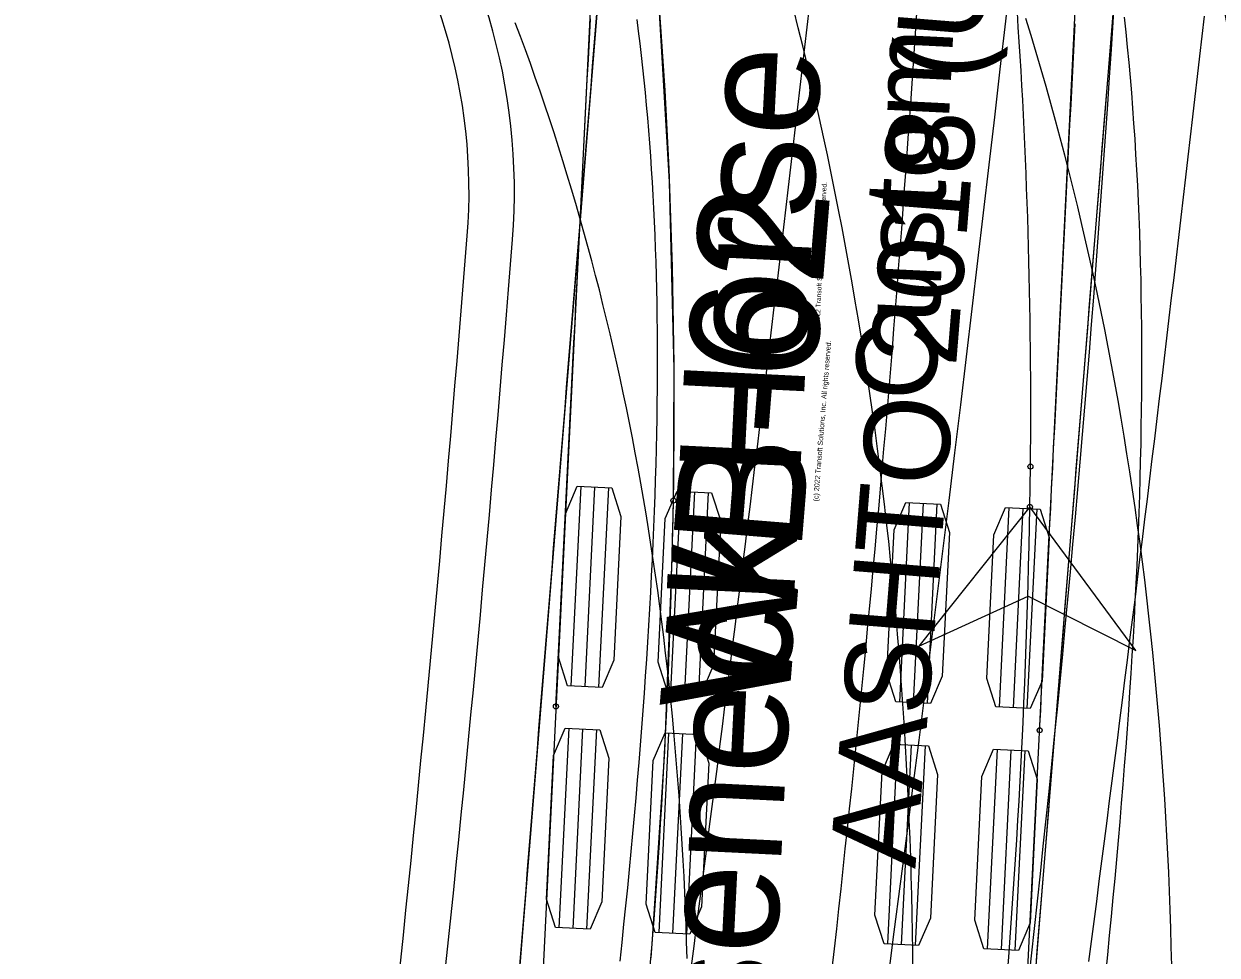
# Model space of a CAD drawing. Extents: x -14 to 1565148, y -25 to 642856.
# Drawn here: x 1564799.31 to 1564819.02, y 636248.55 to 636263.93 of the extents above; entities that cross this region are included whole.
import ezdxf

# ---------------------------------------------------------------- set-up
doc = ezdxf.new("R2010")
doc.units = 0
for name, color, linetype in [('GE_X_Alignment', 7, 'Continuous'), ('MT_P_Cells', 7, 'Continuous'), ('PF_P_Grade_Line', 7, 'Continuous'), ('PV_P_Curb', 7, 'Continuous'), ('PV_P_EOP', 7, 'Continuous'), ('TR_Turning_Path25', 7, 'Continuous'), ('TR_Turning_Path27', 7, 'Continuous')]:
    doc.layers.add(name, color=color, linetype=linetype)

msp = doc.modelspace()

# ---------------------------------------------------------------- linework, layer by layer
at = {"layer": 'GE_X_Alignment'}
for centre, radius, start, end in [((1564797.408, 636261.157), 9.25, 355.4736, 79.0428), ((1564323.889, 636298.643), 484.25, 352.33607, 355.47361)]:
    msp.add_arc(centre, radius, start, end, dxfattribs=at)
at = {"layer": 'MT_P_Cells'}
for points in [[(1564810.331, 636248.364), (1564810.375, 636248.694), (1564810.418, 636249.024), (1564810.461, 636249.353), (1564810.504, 636249.683), (1564810.547, 636250.013), (1564810.59, 636250.343), (1564810.633, 636250.673), (1564810.675, 636251.002), (1564810.718, 636251.332), (1564810.76, 636251.662), (1564810.802, 636251.992), (1564810.844, 636252.322), (1564810.886, 636252.652), (1564810.928, 636252.982), (1564810.97, 636253.311), (1564811.012, 636253.641), (1564811.053, 636253.971), (1564811.094, 636254.301), (1564811.136, 636254.631), (1564811.177, 636254.961), (1564811.218, 636255.291), (1564811.259, 636255.621), (1564811.3, 636255.951), (1564811.34, 636256.281), (1564811.381, 636256.611), (1564811.421, 636256.942), (1564811.462, 636257.272), (1564811.502, 636257.602), (1564811.542, 636257.932), (1564811.582, 636258.262), (1564811.622, 636258.592), (1564811.661, 636258.922), (1564811.701, 636259.253), (1564811.74, 636259.583), (1564811.78, 636259.913), (1564811.819, 636260.243), (1564811.858, 636260.573), (1564811.897, 636260.904), (1564811.936, 636261.234), (1564811.975, 636261.564), (1564812.013, 636261.894), (1564812.052, 636262.225), (1564812.09, 636262.555), (1564812.129, 636262.885), (1564812.167, 636263.216), (1564812.205, 636263.546), (1564812.243, 636263.877), (1564812.28, 636264.207)], [(1564809.155, 636248.448), (1564809.187, 636248.752), (1564809.218, 636249.056), (1564809.249, 636249.358), (1564809.279, 636249.659), (1564809.308, 636249.959), (1564809.336, 636250.257), (1564809.364, 636250.554), (1564809.391, 636250.849), (1564809.417, 636251.143), (1564809.442, 636251.435), (1564809.466, 636251.726), (1564809.49, 636252.015), (1564809.512, 636252.303), (1564809.534, 636252.589), (1564809.555, 636252.873), (1564809.575, 636253.156), (1564809.594, 636253.437), (1564809.612, 636253.716), (1564809.63, 636253.993), (1564809.646, 636254.268), (1564809.661, 636254.542), (1564809.675, 636254.813), (1564809.689, 636255.083), (1564809.701, 636255.35), (1564809.713, 636255.615), (1564809.723, 636255.879), (1564809.733, 636256.14), (1564809.741, 636256.399), (1564809.748, 636256.656), (1564809.755, 636256.91), (1564809.76, 636257.163), (1564809.765, 636257.413), (1564809.768, 636257.66), (1564809.77, 636257.906), (1564809.772, 636258.148), (1564809.772, 636258.389), (1564809.772, 636258.627), (1564809.77, 636258.862), (1564809.767, 636259.092), (1564809.764, 636259.32), (1564809.759, 636259.548), (1564809.754, 636259.774), (1564809.748, 636259.998), (1564809.74, 636260.221), (1564809.732, 636260.443), (1564809.722, 636260.664), (1564809.712, 636260.883), (1564809.7, 636261.101), (1564809.688, 636261.318), (1564809.674, 636261.533), (1564809.66, 636261.747), (1564809.644, 636261.959), (1564809.628, 636262.17), (1564809.61, 636262.38), (1564809.592, 636262.588), (1564809.572, 636262.795), (1564809.552, 636263), (1564809.53, 636263.204), (1564809.508, 636263.407), (1564809.484, 636263.608), (1564809.459, 636263.808), (1564809.434, 636264.006)], [(1564816.896, 636248.438), (1564816.939, 636248.77), (1564816.983, 636249.102), (1564817.026, 636249.434), (1564817.069, 636249.766), (1564817.112, 636250.098), (1564817.155, 636250.43), (1564817.197, 636250.763), (1564817.24, 636251.095), (1564817.282, 636251.427), (1564817.325, 636251.759), (1564817.367, 636252.091), (1564817.409, 636252.424), (1564817.451, 636252.756), (1564817.493, 636253.088), (1564817.534, 636253.42), (1564817.576, 636253.753), (1564817.617, 636254.085), (1564817.659, 636254.417), (1564817.7, 636254.75), (1564817.741, 636255.082), (1564817.782, 636255.414), (1564817.823, 636255.747), (1564817.864, 636256.079), (1564817.904, 636256.412), (1564817.945, 636256.744), (1564817.985, 636257.077), (1564818.025, 636257.409), (1564818.066, 636257.742), (1564818.106, 636258.074), (1564818.145, 636258.407), (1564818.185, 636258.739), (1564818.225, 636259.072), (1564818.264, 636259.404), (1564818.304, 636259.737), (1564818.343, 636260.069), (1564818.382, 636260.402), (1564818.421, 636260.735), (1564818.46, 636261.067), (1564818.499, 636261.4), (1564818.538, 636261.732), (1564818.576, 636262.065), (1564818.615, 636262.398), (1564818.653, 636262.731), (1564818.691, 636263.063), (1564818.73, 636263.396), (1564818.768, 636263.729), (1564818.805, 636264.061)], [(1564817.176, 636248.236), (1564817.208, 636248.553), (1564817.24, 636248.869), (1564817.27, 636249.184), (1564817.3, 636249.499), (1564817.329, 636249.812), (1564817.358, 636250.125), (1564817.385, 636250.437), (1564817.412, 636250.748), (1564817.438, 636251.058), (1564817.463, 636251.367), (1564817.488, 636251.674), (1564817.511, 636251.981), (1564817.534, 636252.286), (1564817.555, 636252.591), (1564817.576, 636252.894), (1564817.595, 636253.196), (1564817.614, 636253.496), (1564817.632, 636253.796), (1564817.649, 636254.094), (1564817.664, 636254.39), (1564817.679, 636254.685), (1564817.693, 636254.979), (1564817.705, 636255.271), (1564817.717, 636255.562), (1564817.727, 636255.851), (1564817.737, 636256.138), (1564817.745, 636256.424), (1564817.752, 636256.708), (1564817.758, 636256.99), (1564817.763, 636257.271), (1564817.767, 636257.55), (1564817.77, 636257.827), (1564817.772, 636258.102), (1564817.772, 636258.375), (1564817.772, 636258.646), (1564817.77, 636258.915), (1564817.767, 636259.179), (1564817.763, 636259.441), (1564817.758, 636259.704), (1564817.752, 636259.965), (1564817.744, 636260.226), (1564817.736, 636260.486), (1564817.726, 636260.746), (1564817.715, 636261.004), (1564817.703, 636261.262), (1564817.689, 636261.519), (1564817.675, 636261.775), (1564817.659, 636262.031), (1564817.642, 636262.285), (1564817.623, 636262.539), (1564817.604, 636262.792), (1564817.583, 636263.044), (1564817.561, 636263.295), (1564817.537, 636263.545), (1564817.512, 636263.795), (1564817.486, 636264.043)]]:
    msp.add_lwpolyline(points, dxfattribs=at)
msp.add_arc((1563898.73, 636368.57), 922.742, 351.014658, 354.185106, dxfattribs=at)
at = {"layer": 'PF_P_Grade_Line'}
for points in [[(1564812.657, 636248.323), (1564812.694, 636248.652), (1564812.731, 636248.982), (1564812.767, 636249.312), (1564812.803, 636249.642), (1564812.839, 636249.972), (1564812.874, 636250.302), (1564812.909, 636250.632), (1564812.944, 636250.962), (1564812.979, 636251.292), (1564813.013, 636251.622), (1564813.047, 636251.952), (1564813.08, 636252.282), (1564813.113, 636252.613), (1564813.146, 636252.943), (1564813.178, 636253.273), (1564813.21, 636253.603), (1564813.242, 636253.934), (1564813.273, 636254.264), (1564813.304, 636254.594), (1564813.335, 636254.925), (1564813.365, 636255.255), (1564813.396, 636255.586), (1564813.425, 636255.916), (1564813.455, 636256.247), (1564813.484, 636256.577), (1564813.512, 636256.908), (1564813.541, 636257.239), (1564813.569, 636257.569), (1564813.596, 636257.9), (1564813.624, 636258.231), (1564813.651, 636258.562), (1564813.677, 636258.892), (1564813.704, 636259.223), (1564813.73, 636259.554), (1564813.755, 636259.885), (1564813.781, 636260.216), (1564813.806, 636260.547), (1564813.83, 636260.878), (1564813.854, 636261.208), (1564813.878, 636261.539), (1564813.902, 636261.87), (1564813.925, 636262.202), (1564813.948, 636262.533), (1564813.971, 636262.864), (1564813.993, 636263.195), (1564814.015, 636263.526), (1564814.037, 636263.857), (1564814.058, 636264.188)], [(1564810.26, 636248.491), (1564810.253, 636248.763), (1564810.244, 636249.034), (1564810.234, 636249.304), (1564810.222, 636249.574), (1564810.21, 636249.843), (1564810.196, 636250.111), (1564810.181, 636250.379), (1564810.165, 636250.646), (1564810.148, 636250.912), (1564810.129, 636251.178), (1564810.109, 636251.443), (1564810.088, 636251.707), (1564810.066, 636251.971), (1564810.042, 636252.234), (1564810.018, 636252.496), (1564809.992, 636252.757), (1564809.965, 636253.018), (1564809.936, 636253.278), (1564809.906, 636253.537), (1564809.875, 636253.796), (1564809.843, 636254.054), (1564809.81, 636254.311), (1564809.775, 636254.568), (1564809.739, 636254.823), (1564809.701, 636255.078), (1564809.663, 636255.332), (1564809.623, 636255.586), (1564809.582, 636255.839), (1564809.539, 636256.09), (1564809.496, 636256.342), (1564809.451, 636256.592), (1564809.404, 636256.842), (1564809.357, 636257.091), (1564809.308, 636257.339), (1564809.258, 636257.586), (1564809.206, 636257.833), (1564809.154, 636258.078), (1564809.1, 636258.323), (1564809.045, 636258.567), (1564808.988, 636258.811), (1564808.93, 636259.053), (1564808.871, 636259.295), (1564808.811, 636259.536), (1564808.749, 636259.776), (1564808.686, 636260.015), (1564808.622, 636260.253), (1564808.557, 636260.491), (1564808.49, 636260.728), (1564808.422, 636260.964), (1564808.352, 636261.199), (1564808.282, 636261.433), (1564808.21, 636261.666), (1564808.137, 636261.898), (1564808.062, 636262.13), (1564807.987, 636262.361), (1564807.91, 636262.59), (1564807.831, 636262.819), (1564807.752, 636263.047), (1564807.671, 636263.274), (1564807.589, 636263.5), (1564807.506, 636263.725), (1564807.421, 636263.95)], [(1564818.265, 636248.376), (1564818.258, 636248.683), (1564818.249, 636248.99), (1564818.239, 636249.296), (1564818.228, 636249.602), (1564818.215, 636249.908), (1564818.201, 636250.213), (1564818.186, 636250.518), (1564818.169, 636250.823), (1564818.151, 636251.127), (1564818.131, 636251.431), (1564818.11, 636251.735), (1564818.087, 636252.038), (1564818.063, 636252.34), (1564818.038, 636252.643), (1564818.011, 636252.945), (1564817.982, 636253.246), (1564817.953, 636253.547), (1564817.921, 636253.848), (1564817.889, 636254.148), (1564817.854, 636254.447), (1564817.819, 636254.747), (1564817.781, 636255.045), (1564817.743, 636255.344), (1564817.702, 636255.641), (1564817.661, 636255.939), (1564817.617, 636256.235), (1564817.572, 636256.532), (1564817.526, 636256.827), (1564817.478, 636257.122), (1564817.429, 636257.417), (1564817.378, 636257.711), (1564817.325, 636258.005), (1564817.271, 636258.297), (1564817.215, 636258.59), (1564817.158, 636258.881), (1564817.099, 636259.173), (1564817.039, 636259.463), (1564816.977, 636259.753), (1564816.913, 636260.042), (1564816.848, 636260.331), (1564816.781, 636260.619), (1564816.713, 636260.906), (1564816.643, 636261.193), (1564816.571, 636261.479), (1564816.498, 636261.764), (1564816.424, 636262.048), (1564816.347, 636262.332), (1564816.269, 636262.615), (1564816.19, 636262.898), (1564816.109, 636263.179), (1564816.026, 636263.46), (1564815.942, 636263.74), (1564815.856, 636264.02)]]:
    msp.add_lwpolyline(points, dxfattribs=at)
msp.add_arc((1564490.246, 636284.79), 327.714, 352.53249, 357.63053, dxfattribs=at)
at = {"layer": 'PV_P_Curb'}
for points in [[(1564810.034, 636256.055), (1564810.046, 636258.226), (1564809.971, 636261.319), (1564809.79, 636264.407), (1564809.501, 636267.487), (1564809.106, 636270.555), (1564809.014, 636271.167)], [(1564809.665, 636248.499), (1564809.69, 636248.816), (1564809.714, 636249.133), (1564809.737, 636249.449), (1564809.759, 636249.766), (1564809.781, 636250.082), (1564809.802, 636250.398), (1564809.822, 636250.714), (1564809.841, 636251.03), (1564809.859, 636251.346), (1564809.876, 636251.662), (1564809.893, 636251.977), (1564809.909, 636252.293), (1564809.924, 636252.608), (1564809.938, 636252.923), (1564809.951, 636253.237), (1564809.964, 636253.552), (1564809.975, 636253.866), (1564809.986, 636254.182), (1564809.996, 636254.496), (1564810.005, 636254.811), (1564810.014, 636255.125), (1564810.021, 636255.441), (1564810.028, 636255.756), (1564810.034, 636256.073), (1564810.039, 636256.389), (1564810.043, 636256.708), (1564810.046, 636257.024), (1564810.047, 636257.344), (1564810.048, 636257.662), (1564810.047, 636257.984), (1564810.045, 636258.303), (1564810.042, 636258.626), (1564810.038, 636258.946), (1564810.033, 636259.27), (1564810.026, 636259.592), (1564810.018, 636259.917), (1564810.01, 636260.239), (1564809.999, 636260.565), (1564809.988, 636260.888), (1564809.976, 636261.214), (1564809.962, 636261.537), (1564809.947, 636261.862), (1564809.931, 636262.185), (1564809.914, 636262.51), (1564809.896, 636262.832), (1564809.876, 636263.155), (1564809.856, 636263.476), (1564809.834, 636263.797), (1564809.811, 636264.116)], [(1564812.986, 636259.651), (1564812.932, 636259.954), (1564812.877, 636260.256), (1564812.82, 636260.559), (1564812.761, 636260.861), (1564812.701, 636261.163), (1564812.64, 636261.464), (1564812.577, 636261.766), (1564812.513, 636262.066), (1564812.447, 636262.367), (1564812.38, 636262.667), (1564812.312, 636262.967), (1564812.242, 636263.267), (1564812.17, 636263.566), (1564812.097, 636263.865), (1564812.023, 636264.163)], [(1564813.991, 636248.304), (1564813.988, 636248.613), (1564813.984, 636248.922), (1564813.978, 636249.23), (1564813.971, 636249.539), (1564813.963, 636249.848), (1564813.954, 636250.156), (1564813.943, 636250.465), (1564813.931, 636250.773), (1564813.918, 636251.081), (1564813.903, 636251.389), (1564813.887, 636251.697), (1564813.87, 636252.005), (1564813.851, 636252.313), (1564813.831, 636252.621), (1564813.81, 636252.928), (1564813.787, 636253.236), (1564813.763, 636253.543), (1564813.738, 636253.85), (1564813.711, 636254.157), (1564813.683, 636254.464), (1564813.653, 636254.771), (1564813.622, 636255.077), (1564813.59, 636255.383), (1564813.556, 636255.69), (1564813.521, 636255.996), (1564813.484, 636256.301), (1564813.446, 636256.607), (1564813.407, 636256.912), (1564813.366, 636257.218), (1564813.323, 636257.523), (1564813.28, 636257.827), (1564813.234, 636258.132), (1564813.188, 636258.436), (1564813.14, 636258.74), (1564813.09, 636259.044), (1564813.039, 636259.348), (1564812.986, 636259.651)], [(1564815.923, 636255.95), (1564815.928, 636256.283), (1564815.932, 636256.617)], [(1564809.393, 636245.549), (1564809.683, 636248.729), (1564809.89, 636251.912), (1564810.013, 636255.099), (1564810.034, 636256.055)], [(1564815.923, 636255.95), (1564814.086, 636253.648), (1564815.895, 636254.478), (1564817.671, 636253.58), (1564815.923, 636255.95)]]:
    msp.add_lwpolyline(points, dxfattribs=at)
msp.add_lwpolyline([(1564815.923, 636255.95), (1564814.086, 636253.648), (1564815.895, 636254.478), (1564817.671, 636253.58)], close=True, dxfattribs=at)
for centre in [(1564815.932, 636256.617), (1564815.932, 636256.617), (1564810.034, 636256.055), (1564810.034, 636256.055), (1564815.923, 636255.95), (1564815.923, 636255.95)]:
    msp.add_circle(centre, 0.0417, dxfattribs=at)
for centre, radius, start, end in [((1564760.333, 636253.08), 59.839, 7.57218, 39.87786), ((1564720.886, 636257.63), 95.051, 359.38909, 8.73292), ((1564687.778, 636258.238), 128.165, 354.34466, 358.9773)]:
    msp.add_arc(centre, radius, start, end, dxfattribs=at)
at = {"layer": 'PV_P_EOP'}
for centre, radius, start, end in [((1564797.408, 636261.157), 10, 355.4736, 79.0428), ((1564797.408, 636261.157), 9.25, 355.4736, 79.0428), ((1564323.889, 636298.643), 484.25, 352.33607, 355.47361), ((1564323.889, 636298.643), 485, 352.33607, 355.47361)]:
    msp.add_arc(centre, radius, start, end, dxfattribs=at)
at = {"layer": 'TR_Turning_Path25'}
for p, q in [((1564809.376, 636278.624), (1564807.601, 636242.667)), ((1564815.591, 636242.273), (1564817.366, 636278.229)), ((1564808.503, 636256.289), (1564808.34, 636252.993)), ((1564808.732, 636256.278), (1564808.569, 636252.982)), ((1564808.96, 636256.267), (1564808.798, 636252.971)), ((1564810.151, 636256.208), (1564809.988, 636252.912)), ((1564810.38, 636256.197), (1564810.217, 636252.901)), ((1564810.608, 636256.186), (1564810.446, 636252.89)), ((1564813.929, 636256.022), (1564813.767, 636252.726)), ((1564814.158, 636256.01), (1564813.996, 636252.714)), ((1564814.387, 636255.999), (1564814.224, 636252.703)), ((1564815.577, 636255.94), (1564815.415, 636252.644)), ((1564815.806, 636255.929), (1564815.644, 636252.633)), ((1564816.035, 636255.918), (1564815.872, 636252.622)), ((1564808.305, 636252.294), (1564808.143, 636248.998)), ((1564808.534, 636252.283), (1564808.372, 636248.987)), ((1564808.763, 636252.272), (1564808.6, 636248.976)), ((1564809.953, 636252.213), (1564809.791, 636248.917)), ((1564810.182, 636252.202), (1564810.02, 636248.906)), ((1564810.411, 636252.19), (1564810.248, 636248.894)), ((1564813.732, 636252.026), (1564813.569, 636248.73)), ((1564813.961, 636252.015), (1564813.798, 636248.719)), ((1564814.19, 636252.004), (1564814.027, 636248.708)), ((1564815.38, 636251.945), (1564815.217, 636248.649)), ((1564815.609, 636251.934), (1564815.446, 636248.638)), ((1564815.838, 636251.922), (1564815.675, 636248.626))]:
    msp.add_line(p, q, dxfattribs=at)
for points in [[(1564808.094, 636252.655), (1564808.11, 636252.988), (1564808.127, 636253.321), (1564808.143, 636253.654), (1564808.16, 636253.988), (1564808.176, 636254.322), (1564808.193, 636254.656), (1564808.209, 636254.99), (1564808.226, 636255.324), (1564808.242, 636255.658), (1564808.259, 636255.992), (1564808.275, 636256.326), (1564808.292, 636256.66), (1564808.309, 636256.994), (1564808.325, 636257.328), (1564808.342, 636257.662), (1564808.359, 636257.996), (1564808.375, 636258.33), (1564808.392, 636258.665), (1564808.409, 636258.999), (1564808.425, 636259.333), (1564808.442, 636259.667), (1564808.459, 636260.001), (1564808.476, 636260.335), (1564808.493, 636260.67), (1564808.51, 636261.004), (1564808.527, 636261.338), (1564808.544, 636261.672), (1564808.561, 636262.007), (1564808.578, 636262.341), (1564808.595, 636262.675), (1564808.612, 636263.01), (1564808.63, 636263.344), (1564808.647, 636263.678), (1564808.664, 636264.013)], [(1564816.084, 636252.261), (1564816.101, 636252.594), (1564816.117, 636252.927), (1564816.133, 636253.259), (1564816.15, 636253.593), (1564816.166, 636253.927), (1564816.183, 636254.261), (1564816.199, 636254.595), (1564816.216, 636254.928), (1564816.232, 636255.262), (1564816.249, 636255.596), (1564816.266, 636255.929), (1564816.282, 636256.263), (1564816.299, 636256.597), (1564816.315, 636256.93), (1564816.332, 636257.264), (1564816.349, 636257.597), (1564816.365, 636257.931), (1564816.382, 636258.265), (1564816.399, 636258.598), (1564816.415, 636258.932), (1564816.432, 636259.265), (1564816.449, 636259.599), (1564816.466, 636259.932), (1564816.483, 636260.266), (1564816.5, 636260.599), (1564816.517, 636260.932), (1564816.534, 636261.266), (1564816.551, 636261.599), (1564816.568, 636261.932), (1564816.585, 636262.266), (1564816.602, 636262.599), (1564816.619, 636262.932), (1564816.636, 636263.266), (1564816.653, 636263.599), (1564816.671, 636263.932)]]:
    msp.add_lwpolyline(points, dxfattribs=at)
for points in [[(1564808.446, 636256.292), (1564809.017, 636256.264), (1564809.167, 636255.794), (1564809.049, 636253.421), (1564808.855, 636252.968), (1564808.283, 636252.996), (1564808.134, 636253.466), (1564808.251, 636255.839)], [(1564810.094, 636256.211), (1564810.665, 636256.183), (1564810.815, 636255.713), (1564810.697, 636253.34), (1564810.503, 636252.887), (1564809.931, 636252.915), (1564809.782, 636253.385), (1564809.899, 636255.758)], [(1564813.873, 636256.024), (1564814.444, 636255.996), (1564814.593, 636255.526), (1564814.476, 636253.153), (1564814.281, 636252.7), (1564813.71, 636252.728), (1564813.561, 636253.198), (1564813.678, 636255.571)], [(1564815.521, 636255.943), (1564816.092, 636255.915), (1564816.241, 636255.445), (1564816.124, 636253.072), (1564815.929, 636252.619), (1564815.358, 636252.647), (1564815.209, 636253.117), (1564815.326, 636255.49)], [(1564808.249, 636252.297), (1564808.82, 636252.269), (1564808.969, 636251.799), (1564808.852, 636249.426), (1564808.657, 636248.973), (1564808.086, 636249.001), (1564807.937, 636249.471), (1564808.054, 636251.844)], [(1564809.897, 636252.216), (1564810.468, 636252.188), (1564810.617, 636251.718), (1564810.5, 636249.345), (1564810.305, 636248.892), (1564809.734, 636248.92), (1564809.585, 636249.39), (1564809.702, 636251.763)], [(1564813.675, 636252.029), (1564814.247, 636252.001), (1564814.396, 636251.531), (1564814.279, 636249.158), (1564814.084, 636248.705), (1564813.513, 636248.733), (1564813.363, 636249.203), (1564813.481, 636251.576)], [(1564815.323, 636251.948), (1564815.895, 636251.92), (1564816.044, 636251.45), (1564815.927, 636249.077), (1564815.732, 636248.624), (1564815.161, 636248.652), (1564815.011, 636249.122), (1564815.129, 636251.495)]]:
    msp.add_lwpolyline(points, close=True, dxfattribs=at)
for centre in [(1564808.094, 636252.655), (1564816.084, 636252.261)]:
    msp.add_circle(centre, 0.0417, dxfattribs=at)
at = {"layer": 'TR_Turning_Path27'}
for p, q in [((1564810.223, 636282.042), (1564806.356, 636234.269)), ((1564814.828, 636233.583), (1564818.695, 636281.357))]:
    msp.add_line(p, q, dxfattribs=at)
for points in [[(1564807.492, 636248.305), (1564807.519, 636248.637), (1564807.546, 636248.968), (1564807.573, 636249.3), (1564807.6, 636249.632), (1564807.626, 636249.964), (1564807.653, 636250.295), (1564807.68, 636250.627), (1564807.707, 636250.959), (1564807.734, 636251.291), (1564807.761, 636251.622), (1564807.788, 636251.954), (1564807.814, 636252.286), (1564807.841, 636252.618), (1564807.868, 636252.949), (1564807.895, 636253.281), (1564807.922, 636253.613), (1564807.949, 636253.945), (1564807.975, 636254.276), (1564808.002, 636254.608), (1564808.029, 636254.94), (1564808.056, 636255.272), (1564808.083, 636255.603), (1564808.11, 636255.935), (1564808.137, 636256.267), (1564808.163, 636256.599), (1564808.19, 636256.93), (1564808.217, 636257.262), (1564808.244, 636257.594), (1564808.271, 636257.926), (1564808.298, 636258.257), (1564808.325, 636258.589), (1564808.351, 636258.921), (1564808.378, 636259.253), (1564808.405, 636259.585), (1564808.432, 636259.916), (1564808.459, 636260.248), (1564808.486, 636260.58), (1564808.512, 636260.912), (1564808.539, 636261.243), (1564808.566, 636261.575), (1564808.593, 636261.907), (1564808.62, 636262.239), (1564808.647, 636262.57), (1564808.674, 636262.902), (1564808.7, 636263.234), (1564808.727, 636263.566), (1564808.754, 636263.897), (1564808.781, 636264.229)], [(1564816.018, 636248.283), (1564816.045, 636248.614), (1564816.072, 636248.946), (1564816.099, 636249.278), (1564816.126, 636249.61), (1564816.152, 636249.941), (1564816.179, 636250.273), (1564816.206, 636250.605), (1564816.233, 636250.937), (1564816.26, 636251.268), (1564816.287, 636251.6), (1564816.314, 636251.932), (1564816.34, 636252.264), (1564816.367, 636252.595), (1564816.394, 636252.927), (1564816.421, 636253.259), (1564816.448, 636253.591), (1564816.475, 636253.923), (1564816.501, 636254.254), (1564816.528, 636254.586), (1564816.555, 636254.918), (1564816.582, 636255.25), (1564816.609, 636255.581), (1564816.636, 636255.913), (1564816.663, 636256.245), (1564816.689, 636256.577), (1564816.716, 636256.908), (1564816.743, 636257.24), (1564816.77, 636257.572), (1564816.797, 636257.904), (1564816.824, 636258.235), (1564816.851, 636258.567), (1564816.877, 636258.899), (1564816.904, 636259.231), (1564816.931, 636259.562), (1564816.958, 636259.894), (1564816.985, 636260.226), (1564817.012, 636260.558), (1564817.038, 636260.889), (1564817.065, 636261.221), (1564817.092, 636261.553), (1564817.119, 636261.885), (1564817.146, 636262.216), (1564817.173, 636262.548), (1564817.2, 636262.88), (1564817.226, 636263.212), (1564817.253, 636263.543), (1564817.28, 636263.875), (1564817.307, 636264.207)]]:
    msp.add_lwpolyline(points, dxfattribs=at)

# ---------------------------------------------------------------- texts
at = {"layer": 'TR_Turning_Path25'}
for s, height, p in [('Gooseneck Horse Trailer', 2, (1564811.42, 636242.145)), ('Custom', 1.3333, (1564814.356, 636257.686)), ('(c) 2022 Transoft Solutions, Inc. All rights reserved.', 0.08, (1564812.443, 636258.81))]:
    msp.add_text(s, height=height, rotation=87.1733, dxfattribs=at).set_placement(p)
at = {"layer": 'TR_Turning_Path27'}
for s, height, p in [('AASHTO 2018 (US)', 1.41667, (1564814.03, 636249.965)), ('WB-62', 2.125, (1564811.925, 636252.496)), ('(c) 2022 Transoft Solutions, Inc. All rights reserved.', 0.085, (1564812.425, 636256.039))]:
    msp.add_text(s, height=height, rotation=85.3729, dxfattribs=at).set_placement(p)

doc.saveas('drawing.dxf')
